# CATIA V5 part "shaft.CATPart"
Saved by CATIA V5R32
Part number: Part1
Bounding box of the stored display mesh (mm): x -100 to 100, y -25 to 25, z -24.818 to 24.818
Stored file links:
  D:\PROJECTS\Project 2022\CATIA V5 6R 2022\Resources\Part Files\c16_catia_v5_6r2022_prt\Cylindrical Joint(Fig16-18)\shaft.CATPart
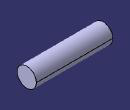
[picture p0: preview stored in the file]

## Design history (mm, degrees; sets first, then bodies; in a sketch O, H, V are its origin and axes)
Body1 (main body)
  Sketch1 on yz-plane, origin (0, 0, 0), H (0, 1, 0), V (0, 0, 1)
    circle A1 centre (0, 0) radius 25
    radius A1 = 25
  Pad1: profile Sketch1, direction (1, 0, 0), length 100, mirrored extent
